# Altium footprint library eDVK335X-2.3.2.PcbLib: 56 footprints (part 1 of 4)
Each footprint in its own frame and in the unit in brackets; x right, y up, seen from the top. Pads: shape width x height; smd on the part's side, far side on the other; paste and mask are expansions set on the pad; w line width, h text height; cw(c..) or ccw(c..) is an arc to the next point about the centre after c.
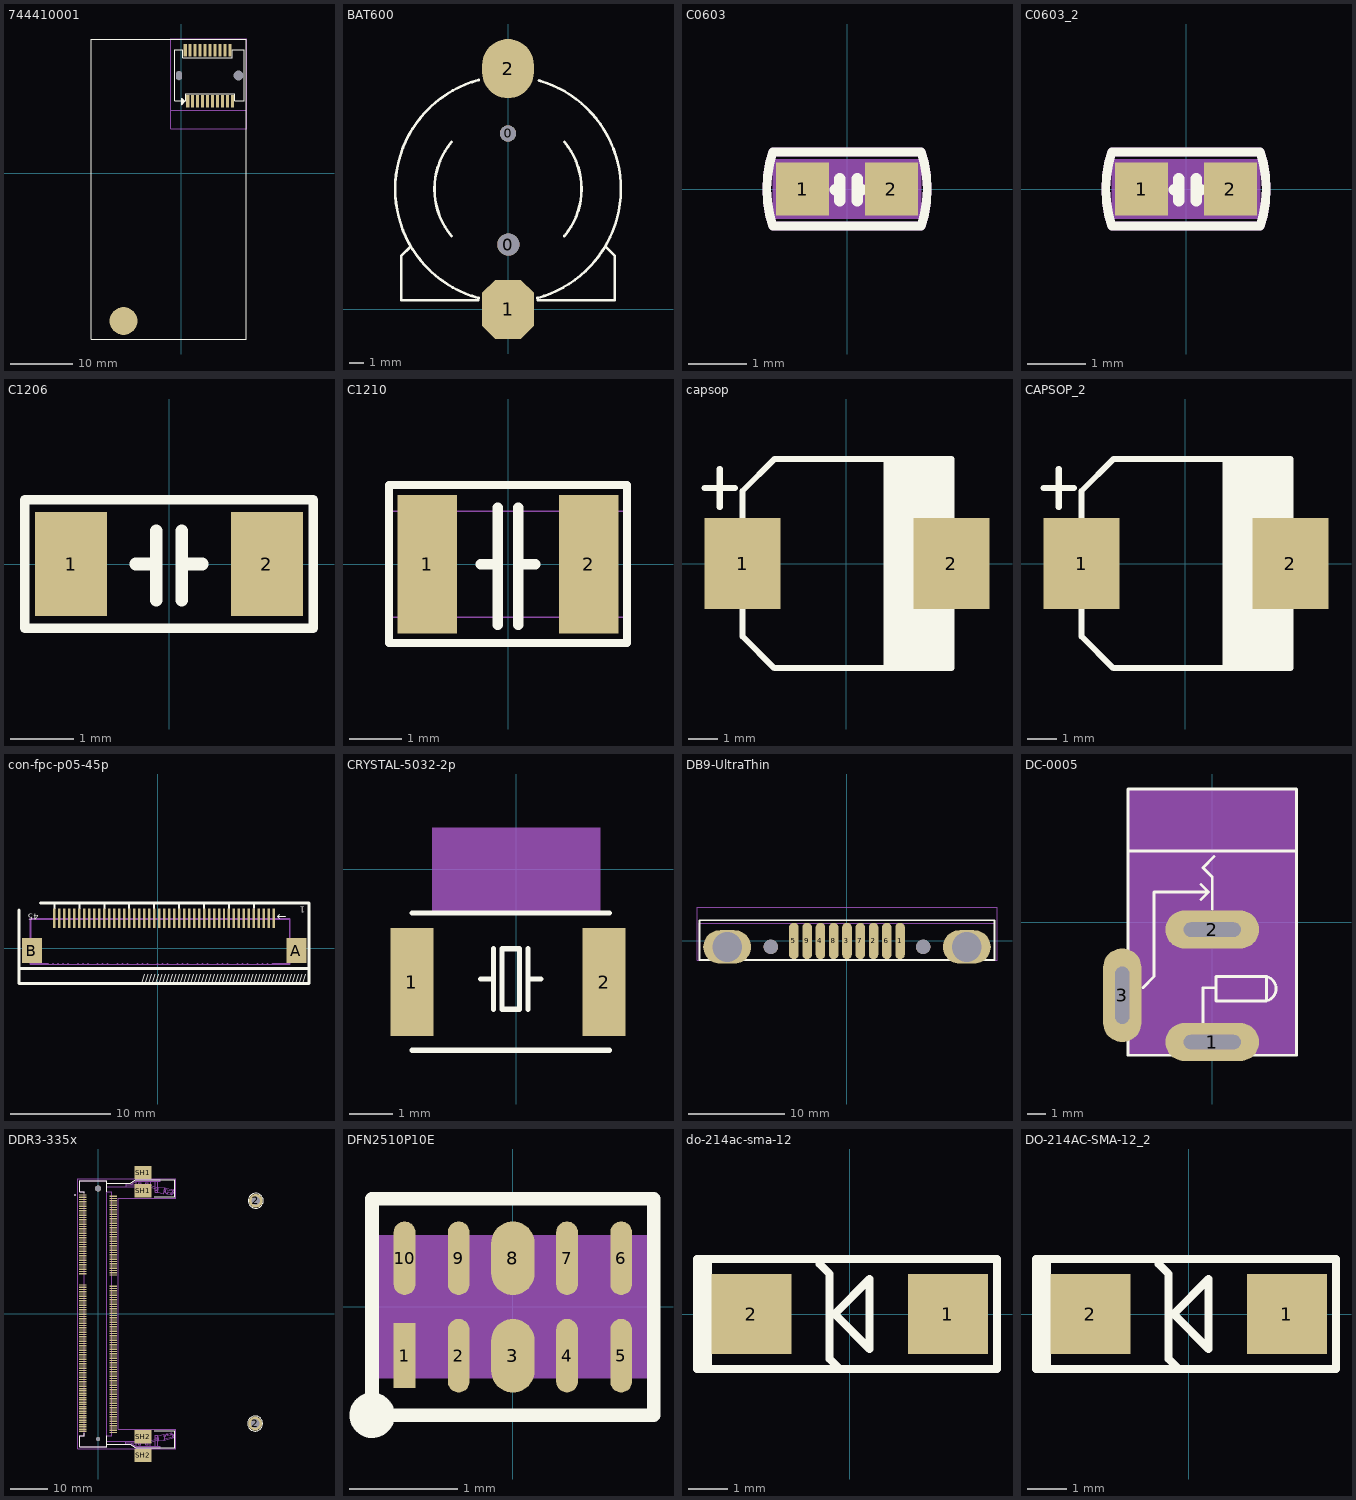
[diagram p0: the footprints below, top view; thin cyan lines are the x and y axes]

## 744410001 [mil] "MINI_PCIEX1-52P-2H-2"
pads (23):
  round 0 hole 37.4 slot 57.09 at 90 deg unplated: 0(-13.11,619.51)
  round 0 hole 62.99 unplated: 0(364.84,619.51)
  rect 20x79 smd: 1(42.01,458.09) 2(26.26,780.93) 3(73.5,458.09) 4(57.76,780.93) 5(105,458.09) 6(89.25,780.93) 7(136.5,458.09) 8(120.75,780.93) 9(167.99,458.09) 10(152.24,780.93) 11(199.49,458.09) 12(183.74,780.93) 13(230.98,458.09) 14(215.24,780.93) 15(262.48,458.09) 16(246.73,780.93) 17(293.98,458.09) 18(278.23,780.93) 19(325.47,458.09) 20(309.73,780.93)
  round 177.16 / inner round 60 / far side round 118.11 all layers, no hole: eMode_PIL(-364.84,-937.58)
Top Overlay:
  rectangle: 15,450.93 20,460.93
  rectangle: 10,443.43 15,468.43
  rectangle: 5,440.93 10,473.43
  lines w5: 5,455.93 25,455.93 ; 15,465.93 15,445.93 10,440.93 10,470.93 ; 10,470.93 5,475.93 5,435.93 25,455.93 ; 10,470.93 25,455.93 ; -569.84,-1052.15 415.16,-1052.15 415.16,849.07 -569.84,849.07 -569.84,-1052.15 ; -39.84,459.07 30.16,459.07 30.16,504.07 340.16,504.07 340.16,459.07 400.16,459.07 400.16,784.07 325.16,784.07 325.16,734.07 20.16,734.07 10.16,734.07 10.16,784.07 -39.84,784.07 -39.84,459.07
Mechanical 1:
  lines w5: -64.84,399.07 415.16,399.07 ; -65.47,280.93 -65.47,851.79 416.81,851.79 416.81,280.93 -65.47,280.93
3D body: height 211.42, standoff 0, extent -39.84,459.07 400.16,783.13

## BAT600 [mm]
pads (4):
  round 1.1 hole 1.1 unplated: 0(0,11.878)
  round 1.5 hole 1.5 unplated: 0(0.025,4.378)
  oct 3.5x4 smd: 1(0,0)
  oval 3.5x4 smd: 2(0,16.256)
Top Overlay:
  lines w0.178: -6.6,4.228 -7.2,3.628 -7.2,0.628 -2,0.628 ; -3.815,4.959 cw(c0,8.128) -3.812,11.3 ; -1.963,0.765 cw(c0,8.128) -7.62,8.128 cw(c0,8.128) -1.963,15.491 ; 1.963,0.765 ccw(c0,8.128) 2.093,15.455 ; 2,0.628 7.2,0.628 7.2,3.628 6.625,4.203 ; 3.81,4.953 ccw(c0,8.128) 3.812,11.3

## C0603 [mil]
pads (2):
  rect 36x36 smd mask+2: 1(-30,0) 2(30,0)
Top Overlay:
  lines w6: -50,-25 cw(c23.53,0) -50,25 50,25 cw(c-23.06,0) 50,-25 -50,-25
  lines w7.87: -7.87,-0.49 -4.92,-0.49 ; -4.92,-7.87 -4.92,6.89 ; 6.89,-7.87 6.89,6.89 ; 6.89,-0.49 9.84,-0.49
Mechanical 9:
  region: -50,20 50,20 50,-20 -50,-20
Mechanical 10:
  lines w6: -50,-25 cw(c23.53,0) -50,25 50,25 cw(c-23.53,0) 50,-25 -50,-25

## C0603_2 [mil]
pads (2):
  rect 36x36 smd: 1(-30,0) 2(30,0)
Top Overlay:
  lines w6: -50,-25 cw(c23.53,0) -50,25 50,25 cw(c-23.06,0) 50,-25 -50,-25
  lines w7.87: -7.87,-0.49 -4.92,-0.49 ; -4.92,-7.87 -4.92,6.89 ; 6.89,-7.87 6.89,6.89 ; 6.89,-0.49 9.84,-0.49
Mechanical 9:
  region: -50,20 50,20 50,-20 -50,-20
Mechanical 10:
  lines w6: -50,-25 cw(c23.53,0) -50,25 50,25 cw(c-23.53,0) 50,-25 -50,-25

## C1206 [mil]
pads (2):
  rect 45x65 smd mask+2: 1(-61,0) 2(61,0)
Top Overlay:
  lines w6: -90,-40 -90,40 -65,40 90,40 90,-40 -90,-40
  lines w7.87: -20.67,0 -7.87,0 ; -7.87,-22.64 -7.87,20.67 ; 7.87,-22.64 7.87,20.67 ; 7.87,0 20.67,0
Mechanical 8:
  text "2" at 61,-4 h10
  text "1" at -61,-4 h10
Mechanical 10:
  lines w1: -90,-40 -90,40 90,40 90,-40 -90,-40

## C1210 [mil] "C1206"
pads (2):
  rect 45x105 smd: 1(-61,0) 2(61,0)
Top Overlay:
  lines w6: -90,-59.45 -90,59.84 90,59.84 90,-59.45 -90,-59.45
  lines w7.87: -20.67,0 -7.87,0 ; -7.87,-45.67 -7.87,42.91 ; 7.87,-45.67 7.87,42.91 ; 7.87,0 20.67,0
Mechanical 8:
  text "2" at 61,-4 h10
  text "1" at -61,-4 h10
Mechanical 10:
  lines w1: -90,-40 -90,40 90,40 90,-40 -90,-40

## capsop [mil] "CAPSOP"
pads (2):
  rect 100x120 smd: 1(-136.8,-0.04) 2(138.79,-0.04)
Top Overlay:
  rectangle: 49.21,-138.78 138.79,137.8
  lines w8: -186.8,99.81 -146.8,99.81 ; -166.8,74.81 -166.8,124.81 ; -136.8,-95.87 -136.8,95.8 -94.8,137.79 138.79,137.79 138.79,-137.8 -94.8,-137.8 -136.8,-95.87
Mechanical 8:
  text "1" at -136.8,9.96 h25
  text "2" at 138.79,9.96 h25
Mechanical 10:
  text "100uF/35V" at -46.8,-50.04 h25
  text ".Designator" at -31.8,29.96 h25

## CAPSOP_2 [mil]
pads (2):
  rect 100x120 smd: 1(-136.8,-0.04) 2(138.79,-0.04)
Top Overlay:
  rectangle: 49.21,-138.78 138.79,137.8
  lines w8: -186.8,99.81 -146.8,99.81 ; -166.8,74.81 -166.8,124.81 ; -136.8,-95.87 -94.8,-137.8 138.79,-137.8 138.79,137.79 -94.8,137.79 -136.8,95.8 -136.8,-95.87
Mechanical 8:
  text "2" at 138.79,9.96 h25
  text "1" at -136.8,9.96 h25
Mechanical 10:
  text ".Designator" at -31.8,29.96 h25
  text "100uF/35V" at -46.8,-50.04 h25

## con-fpc-p05-45p [mm] "CON-FPC-P05-45P"
pads (47):
  rect 0.25x2 smd: 1(11.626,2.989) 2(11.126,2.989) 3(10.626,2.989) 4(10.126,2.989) 5(9.626,2.989) 6(9.126,2.989) 7(8.626,2.989) 8(8.126,2.989) 9(7.626,2.989) 10(7.126,2.989) 11(6.626,2.989) 12(6.126,2.989) 13(5.626,2.989) 14(5.126,2.989) 15(4.626,2.989) 16(4.126,2.989) 17(3.626,2.989) 18(3.126,2.989) 19(2.626,2.989) 20(2.126,2.989) 21(1.626,2.989) 22(1.126,2.989) 23(0.626,2.989) 24(0.126,2.989) 25(-0.374,2.989) 26(-0.874,2.989) 27(-1.374,2.989) 28(-1.874,2.989) 29(-2.374,2.989) 30(-2.874,2.989) 31(-3.374,2.989) 32(-3.874,2.989) 33(-4.374,2.989) 34(-4.874,2.989) 35(-5.374,2.989) 36(-5.874,2.989) 37(-6.374,2.989) 38(-6.874,2.989) 39(-7.374,2.989) 40(-7.874,2.989) 41(-8.374,2.989) 42(-8.874,2.989) 43(-9.374,2.989) 44(-9.874,2.989) 45(-10.374,2.989)
  rect 2x2.5 smd: A(13.875,-0.25) B(-12.625,-0.25)
Top Overlay:
  lines w0.2: -10.374,3.964 -10.374,4.464 ; -7.874,3.964 -7.874,4.464 ; -5.374,3.964 -5.374,4.464 ; -2.874,3.964 -2.874,4.464 ; -0.374,3.964 -0.374,4.464 ; 2.126,3.964 2.126,4.464 ; 4.626,3.989 4.626,4.489 ; 7.126,3.989 7.126,4.514 ; 9.626,4.014 9.626,4.514
  lines w0.3: -13.925,3.81 -13.925,-2.036 ; -11.755,4.514 15.15,4.514 15.15,-2.036 ; -13.925,-2.036 15.15,-2.036 ; -13.925,-2.036 -13.925,-3.536 15.15,-3.536 15.15,-2.036
  text "///////////////////////////////////////////////" at 14.85,-2.5 h1.3
  text "→" at 12.9,3.825 h1.52
  text "1" at 14.75,4.125 h0.64
  text "45" at -11.965,3.46 h0.64
Mechanical 1:
  lines w0.025: -12.8,-1.603 13.218,-1.603 13.218,2.897 -12.775,2.897 ; -12.782,-1.603 -12.782,2.897
Mechanical 14:
  lines w0.2: -12.8,2.897 13.218,2.897 13.218,0.997 ; -12.782,-1.403 -12.782,-1.603 -11.032,-1.603 ; -12.782,0.997 -12.782,2.897 ; -11.532,-1.603 -11.532,-1.603 ; -9.532,-1.603 -9.532,-1.603 ; -8.032,-1.603 -8.032,-1.603 ; -6.032,-1.603 -6.032,-1.603 ; -5.033,-1.603 -5.032,-1.603 ; -3.033,-1.603 -3.032,-1.603 ; -1.532,-1.603 -1.532,-1.603 ; 0.468,-1.603 0.468,-1.603 ; 1.968,-1.603 1.968,-1.603 ; 3.968,-1.603 3.968,-1.603 ; 4.967,-1.603 4.968,-1.603 ; 6.967,-1.603 6.968,-1.603 ; 8.467,-1.603 8.468,-1.603 ; 10.467,-1.603 10.468,-1.603 ; 11.468,-1.603 13.218,-1.603 13.218,-1.403 ; -11.033,-1.603 -11.032,-1.603 ; -12.032,-1.603 -12.032,-1.603 ; -10.533,-1.603 -10.532,-1.603 ; -10.032,-1.603 -10.032,-1.603 ; -9.033,-1.603 -9.032,-1.603 ; -7.532,-1.603 -7.532,-1.603 ; -7.033,-1.603 -7.032,-1.603 ; -5.532,-1.603 -5.532,-1.603 ; -4.032,-1.603 -4.032,-1.603 ; -3.532,-1.603 -3.532,-1.603 ; -2.032,-1.603 -2.032,-1.603 ; -1.033,-1.603 -1.032,-1.603 ; -0.032,-1.603 -0.032,-1.603 ; 0.967,-1.603 0.968,-1.603 ; 2.468,-1.603 2.468,-1.603 ; 2.967,-1.603 2.968,-1.603 ; 4.467,-1.603 4.468,-1.603 ; 5.968,-1.603 5.968,-1.603 ; 6.467,-1.603 6.468,-1.603 ; 7.968,-1.603 7.968,-1.603 ; 8.967,-1.603 8.968,-1.603 ; 9.968,-1.603 9.968,-1.603 ; 10.967,-1.603 10.968,-1.603
  text "J13" at 11.446,-3.66 h0.79

## CRYSTAL-5032-2p [mil] "CRYSTAL-5032-2P"
pads (2):
  rect 39x98.43 smd: 1(-95,-102.99) 2(80,-102.99)
Top Overlay:
  lines w4.72: -95,-165 85,-165 ; -95,-40 85,-40 ; -32.56,-100 -20.75,-100 ; -20.75,-127.56 -20.75,-72.44 ; 10.75,-127.56 10.75,-72.44 ; 10.75,-100 22.56,-100 ; -12.87,-127.56 2.87,-127.56 2.87,-72.44 -12.87,-72.44 -12.87,-127.56
Mechanical 8:
  text "2" at 55.12,-10 h25
  text "1" at -55.12,-10 h25
Mechanical 9:
  region: -76.62,-37.8 76.62,-37.8 76.62,37.8 -76.62,37.8
Mechanical 10:
  lines w1: -62.99,-29.53 62.99,-29.53 62.99,29.53 -62.99,29.53 -62.99,-29.53

## DB9-UltraThin [mm] "SOP, 18-Leads, Body 30.8x4.7mm (max), Pitch 1.38mm, IPC Medium Density"
height 12.55
pads (13):
  oval 1x3.8 smd: 1(5.54,-0.03) 2(2.77,-0.03) 3(0,-0.03) 4(-2.77,-0.03) 5(-5.545,-0.03) 6(4.15,-0.03) 7(1.385,-0.03) 8(-1.385,-0.03) 9(-4.155,-0.03)
  oval 5x3.5 hole 3.1: ""(-12.5,-0.65) ""(12.5,-0.65)
  round 1.5 hole 1.5: ""(-7.95,-0.65) ""(7.95,-0.65)
Top Overlay:
  lines w0.2: -15.4,-2.035 -15.4,2.135 15.4,2.135 15.4,-2.035 -15.4,-2.035
Mechanical 13:
  lines w0.1: 15.4,1.825 15.4,-2.035 -15.405,-2.035 -15.405,1.825 15.405,1.825
Mechanical 15:
  lines w0.1: -0.5,-0.205 0.5,-0.205 ; 0,-0.705 0,0.295 ; -15.65,-2.04 -15.65,3.5 15.65,3.5 15.65,-2.04 -15.65,-2.04
3D body: height 12.55, standoff 0.1, extent -15.43,-2.05 15.405,1.825

## DC-0005 [mil] "DC-0005"
pads (3):
  oval 197x80 / inner oval 196.85x60 / far side oval 197x80 hole 30 slot 120 at 0 deg: 1(0,-251.97)
  oval 197x80 hole 30 slot 120 at 0 deg: 2(0,-15.75)
  oval 80x197 hole 120 slot 30 at 0 deg: 3(-188.97,-153.54)
Top Overlay:
  lines w5.91: -177.16,149.61 177.17,149.61 ; -145.67,-137.79 -122.05,-114.17 -122.05,62.99 -7.87,62.99 ; -23.62,47.24 -7.87,62.99 ; -23.62,78.74 -7.87,62.99 ; -19.68,-212.6 -19.68,-137.79 7.88,-137.79 ; 0,27.56 0,94.49 -19.68,114.17 3.94,137.8 ; 114.17,-165.35 ccw(c107.48,-139.76) 114.17,-114.17 ; 114.17,-165.35 7.88,-165.35 7.88,-114.17 114.17,-114.17 ; 114.17,-165.35 114.17,-114.17 ; -177.16,-279.53 -177.16,279.53 177.17,279.53 177.17,-279.53 -177.16,-279.53
Mechanical 7:
  region: -177.16,-279.53 177.16,-279.53 177.16,279.53 -177.16,279.53
Mechanical 14:
  text "1" at 10,-251.97 h25
  text "3" at -178.98,-153.54 h25
  text "2" at 10,-15.75 h25
Mechanical 15:
  lines w1: -177.16,-279.53 -177.16,279.53 177.17,279.53 177.17,-279.53 -177.16,-279.53
3D body: height 150, standoff 0, extent -177.16,-279.53 177.16,279.53

## DDR3-335x [mm]
pads (212):
  rect 2x0.35 smd: 1(-4.1,31.65) 2(4.1,31.35) 3(-4.1,31.05) 4(4.1,30.75) 5(-4.1,30.45) 6(4.1,30.15) 7(-4.1,29.85) 8(4.1,29.55) 9(-4.1,29.25) 10(4.1,28.95) 11(-4.1,28.65) 12(4.1,28.35) 13(-4.1,28.05) 14(4.1,27.75) 15(-4.1,27.45) 16(4.1,27.15) 17(-4.1,26.85) 18(4.1,26.55) 19(-4.1,26.25) 20(4.1,25.95) 21(-4.1,25.65) 22(4.1,25.35) 23(-4.1,25.05) 24(4.1,24.75) 25(-4.1,24.45) 26(4.1,24.15) 27(-4.1,23.85) 28(4.1,23.55) 29(-4.1,23.25) 30(4.1,22.95) 31(-4.1,22.65) 32(4.1,22.35) 33(-4.1,22.05) 34(4.1,21.75) 35(-4.1,21.45) 36(4.1,21.15) 37(-4.1,20.85) 38(4.1,20.55) 39(-4.1,20.25) 40(4.1,19.95) 41(-4.1,19.65) 42(4.1,19.35) 43(-4.1,19.05) 44(4.1,18.75) 45(-4.1,18.45) 46(4.1,18.15) 47(-4.1,17.85) 48(4.1,17.55) 49(-4.1,17.25) 50(4.1,16.95) 51(-4.1,16.65) 52(4.1,16.35) 53(-4.1,16.05) 54(4.1,15.75) 55(-4.1,15.45) 56(4.1,15.15) 57(-4.1,14.85) 58(4.1,14.55) 59(-4.1,14.25) 60(4.1,13.95) 61(-4.1,13.65) 62(4.1,13.35) 63(-4.1,13.05) 64(4.1,12.75) 65(-4.1,12.45) 66(4.1,12.15) 67(-4.1,11.85) 68(4.1,11.55) 69(-4.1,11.25) 70(4.1,10.95) 71(-4.1,10.65) 72(4.1,10.35) 73(-4.1,7.65) 74(4.1,7.35) 75(-4.1,7.05) 76(4.1,6.75) 77(-4.1,6.45) 78(4.1,6.15) 79(-4.1,5.85) 80(4.1,5.55) 81(-4.1,5.25) 82(4.1,4.95) 83(-4.1,4.65) 84(4.1,4.35) 85(-4.1,4.05) 86(4.1,3.75) 87(-4.1,3.45) 88(4.1,3.15) 89(-4.1,2.85) 90(4.1,2.55) 91(-4.1,2.25) 92(4.1,1.95) 93(-4.1,1.65) 94(4.1,1.35) 95(-4.1,1.05) 96(4.1,0.75) 97(-4.1,0.45) 98(4.1,0.15) 99(-4.1,-0.15) 100(4.1,-0.45) 101(-4.1,-0.75) 102(4.1,-1.05) 103(-4.1,-1.35) 104(4.1,-1.65) 105(-4.1,-1.95) 106(4.1,-2.25) 107(-4.1,-2.55) 108(4.1,-2.85) 109(-4.1,-3.15) 110(4.1,-3.45) 111(-4.1,-3.75) 112(4.1,-4.05) 113(-4.1,-4.35) 114(4.1,-4.65) 115(-4.1,-4.95) 116(4.1,-5.25) 117(-4.1,-5.55) 118(4.1,-5.85) 119(-4.1,-6.15) 120(4.1,-6.45) 121(-4.1,-6.75) 122(4.1,-7.05) 123(-4.1,-7.35) 124(4.1,-7.65) 125(-4.1,-7.95) 126(4.1,-8.25) 127(-4.1,-8.55) 128(4.1,-8.85) 129(-4.1,-9.15) 130(4.1,-9.45) 131(-4.1,-9.75) 132(4.1,-10.05) 133(-4.1,-10.35) 134(4.1,-10.65) 135(-4.1,-10.95) 136(4.1,-11.25) 137(-4.1,-11.55) 138(4.1,-11.85) 139(-4.1,-12.15) 140(4.1,-12.45) 141(-4.1,-12.75) 142(4.1,-13.05) 143(-4.1,-13.35) 144(4.1,-13.65) 145(-4.1,-13.95) 146(4.1,-14.25) 147(-4.1,-14.55) 148(4.1,-14.85) 149(-4.1,-15.15) 150(4.1,-15.45) 151(-4.1,-15.75) 152(4.1,-16.05) 153(-4.1,-16.35) 154(4.1,-16.65) 155(-4.1,-16.95) 156(4.1,-17.25) 157(-4.1,-17.55) 158(4.1,-17.85) 159(-4.1,-18.15) 160(4.1,-18.45) 161(-4.1,-18.75) 162(4.1,-19.05) 163(-4.1,-19.35) 164(4.1,-19.65) 165(-4.1,-19.95) 166(4.1,-20.25) 167(-4.1,-20.55) 168(4.1,-20.85) 169(-4.1,-21.15) 170(4.1,-21.45) 171(-4.1,-21.75) 172(4.1,-22.05) 173(-4.1,-22.35) 174(4.1,-22.65) 175(-4.1,-22.95) 176(4.1,-23.25) 177(-4.1,-23.55) 178(4.1,-23.85) 179(-4.1,-24.15) 180(4.1,-24.45) 181(-4.1,-24.75) 182(4.1,-25.05) 183(-4.1,-25.35) 184(4.1,-25.65) 185(-4.1,-25.95) 186(4.1,-26.25) 187(-4.1,-26.55) 188(4.1,-26.85) 189(-4.1,-27.15) 190(4.1,-27.45) 191(-4.1,-27.75) 192(4.1,-28.05) 193(-4.1,-28.35) 194(4.1,-28.65) 195(-4.1,-28.95) 196(4.1,-29.25) 197(-4.1,-29.55) 198(4.1,-29.85) 199(-4.1,-30.15) 200(4.1,-30.45) 201(-4.1,-30.75) 202(4.1,-31.05) 203(-4.1,-31.35) 204(4.1,-31.65)
  round 3.7 / inner round 0 / far side round 3 hole 2.3: 2(41.877,-29.27) 2(42.04,30.127)
  rect 4.6x3.5 smd: SH1(12,32.8) SH1(12,37.626) SH2(12,-37.753) SH2(12,-32.8)
  round 1.1 hole 1.1 unplated: ""(0,-33.4)
  round 1.6 hole 1.6 unplated: ""(0,33.4)
Top Overlay:
  circle w0.3: c41.877,-29.27 r2
  circle w0.3: c42.04,30.127 r2
  circle w0.2: c-6.119,31.66 r0.1
  lines w0.127: -3.7,-31.9 -3.7,-32.5 -4.85,-32.5 -4.85,-35.5 2.35,-35.5 2.35,-32.5 ; -3.7,32.1 -3.7,32.5 -4.85,32.5 -4.85,35.5 2.35,35.5 2.35,32.5 ; 2.4,-34.85 8.6,-34.85 10,-35.75 20.5,-35.75 20.5,-31.2 15,-31.2 ; 2.4,34.8 8.6,34.8 10,35.7 20.5,35.7 20.5,31.2 15,31.2
Mechanical 13:
  circle w0.2: c-6.119,31.66 r0.1
  lines w0.127: 2.385,33.901 7.465,33.901 7.465,34.353 ; 2.385,34.801 7.465,34.801 ; 7.42,-33.971 13.5,-33.971 16,-33.25 15.9,-32.6 16,-33.8 17.7,-33.7 ; 7.455,33.922 13.535,33.922 16.035,33.201 15.935,32.551 16.035,33.751 17.735,33.651 ; 8.6,-34.402 7.43,-34.402 ; 8.6,-34.4 13.4,-34.4 16,-33.6 ; 8.625,-34.418 10.025,-35.318 16.6,-35.318 16.6,-35.75 10,-35.75 8.6,-34.85 7.43,-34.85 ; 8.635,34.351 13.435,34.351 16.035,33.551 ; 8.635,34.353 7.465,34.353 ; 8.66,34.369 10.06,35.269 16.635,35.269 16.635,35.701 10.035,35.701 8.635,34.801 7.465,34.801 ; 10.16,-35.267 10.16,-31.65 13.97,-31.65 13.97,-35.255 ; 10.195,35.218 10.195,31.601 14.005,31.601 14.005,35.206 ; 15.24,-35.306 15.24,-33.02 ; 15.275,35.257 15.275,32.971 ; 15.875,-35.293 15.875,-33.02 ; 15.91,35.244 15.91,32.971 ; 16,-32.5 17.5,-32.1 17.7,-33.7 ; 16.035,32.451 17.535,32.051 17.735,33.651 ; 17.561,-32.445 ccw(c17.812,-32.396) 18.062,-32.348 ; 17.596,32.396 cw(c17.847,32.347) 18.097,32.299 ; 17.8,-33.3 19.752,-32.824 ; 17.835,33.251 19.787,32.775 ; 17.9,-32.7 17.7,-33.7 ; 17.935,32.651 17.735,33.651 ; 18.049,-32.328 cw(c18.326,-32.387) 18.604,-32.445 ; 18.084,32.279 ccw(c18.361,32.337) 18.639,32.396 ; 18.3,-32.1 19.427,-31.854 ; 18.335,32.051 19.462,31.805 ; 18.6,-32.4 19.2,-32.3 19.383,-32.239 ; 18.635,32.351 19.235,32.251 19.418,32.19 ; 19.384,-32.239 cw(c19.446,-32.429) 19.587,-32.287 19.804,-32.504 cw(c19.662,-32.645) 19.753,-32.823 ; 19.419,32.19 ccw(c19.481,32.38) 19.622,32.238 19.839,32.455 ccw(c19.697,32.596) 19.788,32.774 ; 19.428,-31.854 cw(c19.516,-32.141) 19.728,-31.928 20.103,-32.303 cw(c19.749,-32.656) 19.968,-33.106 ; 19.463,31.805 ccw(c19.551,32.092) 19.763,31.879 20.138,32.254 ccw(c19.784,32.607) 20.003,33.057 ; 19.967,-33.106 17.7,-33.7 ; 20.002,33.057 17.735,33.651 ; 2.35,-34.85 7.43,-34.85 ; 2.35,-34.85 2.35,-33.95 ; 2.35,-34.85 2.35,-35.5 -4.85,-35.5 -4.85,-32.5 -3.7,-32.5 -3.7,32.5 -4.85,32.5 -4.85,35.5 2.35,35.5 2.35,32.5 ; 2.35,-33.95 7.43,-33.95 7.43,-34.402 ; 2.35,-33.95 2.35,-32.5 ; 2.35,-32.5 3.7,-32.5 3.7,32.5 2.35,32.5 ; 2.35,-32.5 2.35,32.5 ; 7.43,-34.85 7.43,-34.402 ; 7.465,34.353 7.465,34.801 ; 15.24,-33.02 15.875,-33.02 ; 15.24,-33.02 15.24,-32.385 15.875,-32.385 15.875,-33.02 ; 15.275,32.971 15.91,32.971 ; 15.275,32.971 15.275,32.336 15.91,32.336 15.91,32.971 ; 10.795,-34.925 11.43,-34.925 11.43,-33.02 12.7,-33.02 12.7,-34.925 13.335,-34.925 13.335,-33.02 12.7,-32.385 11.43,-32.385 10.795,-33.02 10.795,-34.925 ; 10.83,32.971 11.465,32.336 12.735,32.336 13.37,32.971 13.37,34.876 12.735,34.876 12.735,32.971 11.465,32.971 11.465,34.876 10.83,34.876 10.83,32.971
Mechanical 15:
  lines w0.05: -5.35,35.951 -5.35,35.95 ; -5.35,35.95 20.75,35.95 20.75,30.8 5.35,30.8 5.35,-30.8 20.75,-30.8 20.75,-36 -5.35,-36 -5.35,35.95

## DFN2510P10E [mm] "DFN2510P10E"
pads (10):
  rect 0.2x0.6 smd: 1(-1,-0.45)
  oval 0.2x0.68 smd: 2(-0.5,-0.45) 4(0.5,-0.45) 5(1,-0.45) 6(1,0.45) 7(0.5,0.45) 9(-0.5,0.45) 10(-1,0.45)
  oval 0.4x0.68 smd: 3(0,-0.45) 8(0,0.45)
Top Overlay:
  circle w0.16: c-1.3,-1 r0.13
  lines w0.127: -1.3,-1 1.3,-1 1.3,1 -1.3,1 -1.3,-1
Mechanical 9:
  region: -1.34,-0.65 1.34,-0.65 1.34,0.65 -1.34,0.65
Mechanical 10:
  lines w0.025: -1.34,-0.65 1.34,-0.65 1.34,0.65 -1.34,0.65 -1.34,-0.65

## do-214ac-sma-12 [mil] "DO-214AC-SMA-12"
pads (2):
  rect 80x80 smd: 1(98.42,0) 2(-98.42,0)
Top Overlay:
  lines w8: -150,-55 -150,55 ; -136,-55 -153,-55 -153,55 -132.87,55 ; -30,50 -20,40 -20,-45 -10,-55 ; -142,-55 147.64,-55 147.64,55 -141.73,55 -142,54.73 -142,-55 ; -15,0 20,-35 20,35 -15,0
Mechanical 8:
  text "1" at 102.42,0 h10
  text "2" at -86.42,0 h10
Mechanical 10:
  lines w1: -120,-55 120,-55 ; -120,55 120,55

## DO-214AC-SMA-12_2 [mil]
pads (2):
  rect 80x80 smd: 1(98.42,0) 2(-98.42,0)
Top Overlay:
  lines w8: -150,-55 -150,55 ; -136,-55 -153,-55 -153,55 -132.87,55 ; -30,50 -20,40 -20,-45 -10,-55 ; -142,-55 -142,54.73 -141.73,55 147.64,55 147.64,-55 -142,-55 ; -15,0 20,35 20,-35 -15,0
Mechanical 8:
  text "2" at -86.42,0 h10
  text "1" at 102.42,0 h10
Mechanical 10:
  lines w1: -120,-55 120,-55 ; -120,55 120,55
